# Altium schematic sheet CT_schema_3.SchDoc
size 296 x 169 mm
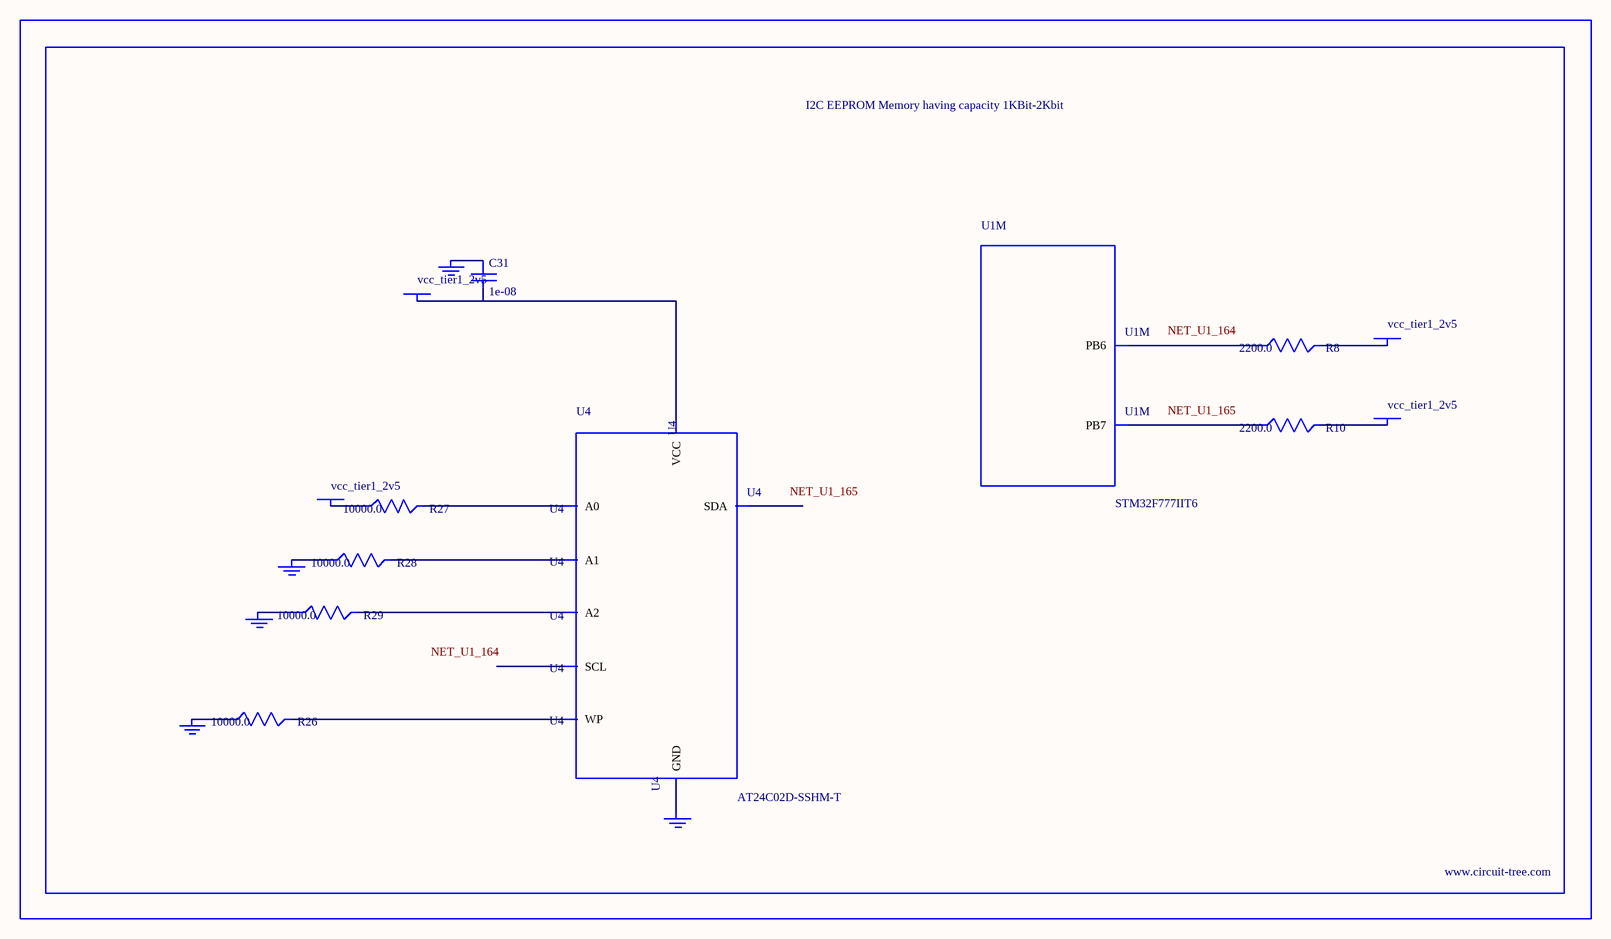
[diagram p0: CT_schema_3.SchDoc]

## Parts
BORDER2  (no value)
C31  1e-08  [C0402]
GND_INSTANCE_2_0  (no value)
GND_INSTANCE_2_1  (no value)
GND_INSTANCE_2_2  (no value)
GND_INSTANCE_2_3  (no value)
GND_INSTANCE_2_4  (no value)
POWER_INSTANCE_2_0  vcc_tier1_2v5
POWER_INSTANCE_2_1  vcc_tier1_2v5
POWER_INSTANCE_2_2  vcc_tier1_2v5
POWER_INSTANCE_2_3  vcc_tier1_2v5
R8  2200.0  [R0603]
R10  2200.0  [R0603]
R26  10000.0  [R0603]
R27  10000.0  [R0603]
R28  10000.0  [R0603]
R29  10000.0  [R0603]
U1  STM32F777IIT6  [LQFP176]  (part M of 15)
U4  AT24C02D-SSHM-T  [AT24C02D]

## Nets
NetC31_1: C31.1 GND_INSTANCE_2_3.0(GND)
NetC31_2: C31.2 POWER_INSTANCE_2_1.0(PWR) U4.8(VCC)
NetGND_INSTANCE_2_0_0: GND_INSTANCE_2_0.0(GND) R28.1
NetGND_INSTANCE_2_1_0: GND_INSTANCE_2_1.0(GND) R29.1
NetGND_INSTANCE_2_2_0: GND_INSTANCE_2_2.0(GND) R26.1
NetGND_INSTANCE_2_4_0: GND_INSTANCE_2_4.0(GND) U4.4(GND)
NetPOWER_INSTANCE_2_0_0: POWER_INSTANCE_2_0.0(PWR) R27.1
NetPOWER_INSTANCE_2_2_0: POWER_INSTANCE_2_2.0(PWR) R8.2
NetPOWER_INSTANCE_2_3_0: POWER_INSTANCE_2_3.0(PWR) R10.2
NetR8_1: R8.1 U1.164(PB6)
NetR10_1: R10.1 U1.165(PB7)
NetR26_2: R26.2 U4.7(WP)
NetR27_2: R27.2 U4.1(A0)
NetR28_2: R28.2 U4.2(A1)
NetR29_2: R29.2 U4.3(A2)

Not connected (* = marked no-connect by the designer): U4 5(SDA) 6(SCL)

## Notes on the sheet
- Labels drawn without touching a wire or pin: NET_U1_164, NET_U1_165

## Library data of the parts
BORDER2 = BORDER_PAGE2
C31 = C0402C103K3RAC
GND_INSTANCE_2_0-GND_INSTANCE_2_4 = GND
POWER_INSTANCE_2_0-POWER_INSTANCE_2_3 = PWR
R8 R10 = RC0603JR-072K2L
R26-R29 = RC0603JR-0710KL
